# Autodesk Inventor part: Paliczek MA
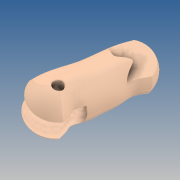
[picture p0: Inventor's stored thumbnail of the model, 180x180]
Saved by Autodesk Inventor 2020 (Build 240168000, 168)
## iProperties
Created: 2019-10
Part Number: Paliczek MA
Material: GFRP
Document SubType Name: Modeling
Designer: yello
Density: 1.75 g/cm^3
Appearance: Default
Author: yello
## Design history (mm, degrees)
feature "Paliczek MA"
sketch "Sketch1"
  geometry: C1 r 2 at (0, 0); 1 further point
  constraints: 1 centre point
  dimensions: "d0" = 4 diameter of C1
extrude "Extrusion1" cut sketch "Sketch1" stored distance "d1" = 100; taper "d2" = 0 deg
body "Solid1"
